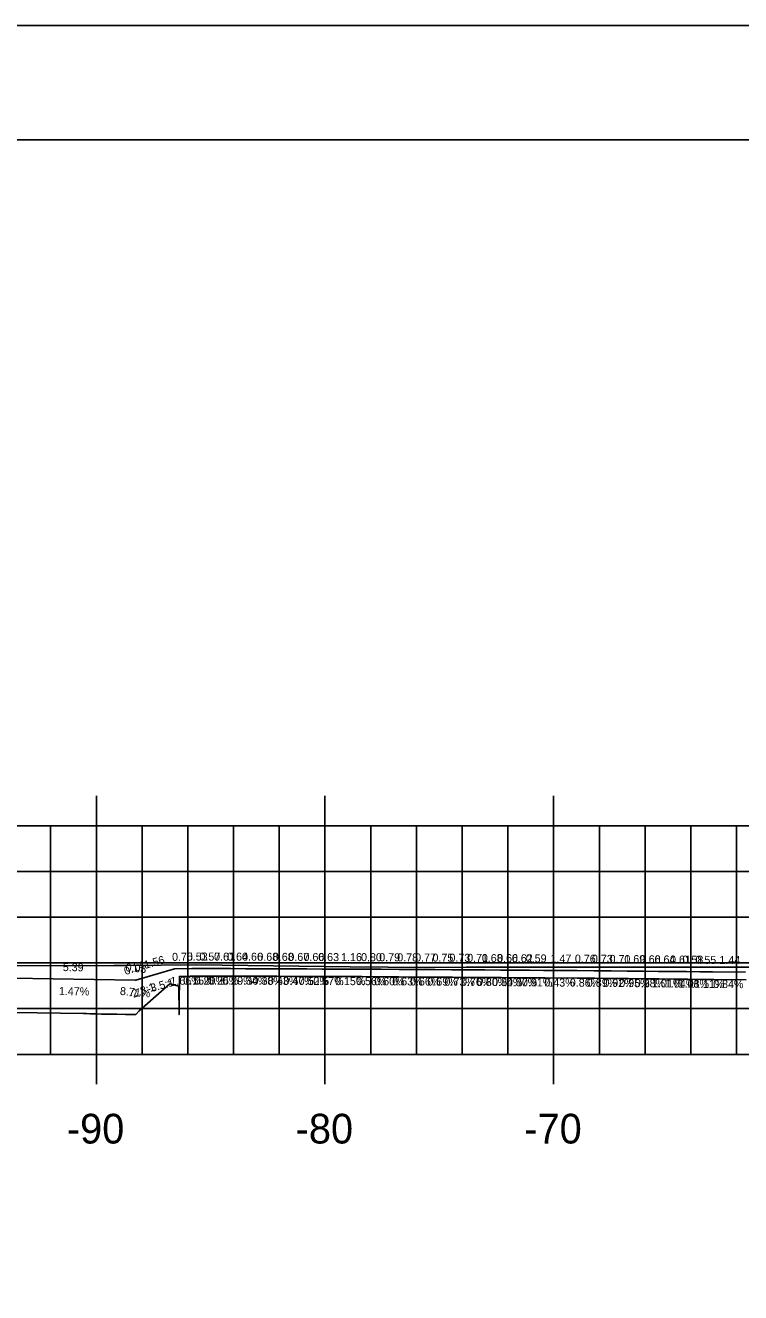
# Model space of a CAD drawing. Extents: x 40011 to 50684, y 49949 to 72236.
# Drawn here: x 41698.9 to 41730.2, y 69139.2 to 69194.6 of the extents above; entities that cross this region are included whole.
import ezdxf

# ---------------------------------------------------------------- set-up
doc = ezdxf.new("R2010")
doc.units = 0
for name, color, linetype in [('1', 7, 'Continuous'), ('10', 7, 'Continuous'), ('41', 7, 'Continuous'), ('51', 7, 'Continuous'), ('53', 7, 'Continuous'), ('55', 7, 'Continuous'), ('57', 7, 'Continuous'), ('58', 7, 'Continuous'), ('59', 7, 'Continuous'), ('60', 7, 'Continuous')]:
    doc.layers.add(name, color=color, linetype=linetype)

msp = doc.modelspace()

# ---------------------------------------------------------------- linework, layer by layer
at = {"layer": '1'}
for p, q in [((41962.978, 69194.597), (41613.588, 69194.597)), ((41961.977, 69189.597), (41631.977, 69189.597))]:
    msp.add_line(p, q, dxfattribs=at)
at = {"layer": '41'}
for points in [[(41613.588, 69194.597), (41962.978, 69194.597), (41962.978, 68974.597), (41613.588, 68974.597)], [(41631.977, 69189.597), (41961.977, 69189.597), (41961.977, 68979.597), (41631.977, 68979.597)]]:
    msp.add_lwpolyline(points, close=True, dxfattribs=at)
at = {"layer": '51'}
for p, q in [((41699.977, 69149.597), (41699.977, 69159.597)), ((41703.977, 69149.597), (41703.977, 69159.597)), ((41705.977, 69149.597), (41705.977, 69159.597)), ((41707.977, 69149.597), (41707.977, 69159.597)), ((41709.977, 69149.597), (41709.977, 69159.597)), ((41713.977, 69149.597), (41713.977, 69159.597)), ((41715.977, 69149.597), (41715.977, 69159.597)), ((41717.977, 69149.597), (41717.977, 69159.597)), ((41719.977, 69149.597), (41719.977, 69159.597)), ((41723.977, 69149.597), (41723.977, 69159.597)), ((41725.977, 69149.597), (41725.977, 69159.597)), ((41727.977, 69149.597), (41727.977, 69159.597)), ((41729.977, 69149.597), (41729.977, 69159.597)), ((41651.977, 69149.597), (41931.977, 69149.597)), ((41701.977, 69148.297), (41701.977, 69149.597)), ((41711.977, 69148.297), (41711.977, 69149.597)), ((41721.977, 69148.297), (41721.977, 69149.597))]:
    msp.add_line(p, q, dxfattribs=at)
at = {"layer": '53'}
for p, q in [((41651.977, 69157.597), (41931.977, 69157.597)), ((41651.977, 69155.597), (41931.977, 69155.597)), ((41651.977, 69153.597), (41931.977, 69153.597)), ((41651.977, 69151.597), (41931.977, 69151.597))]:
    msp.add_line(p, q, dxfattribs=at)
at = {"layer": '55'}
for p, q in [((41651.977, 69159.597), (41931.977, 69159.597)), ((41701.977, 69149.597), (41701.977, 69159.597)), ((41711.977, 69149.597), (41711.977, 69159.597)), ((41721.977, 69149.597), (41721.977, 69159.597)), ((41651.977, 69149.597), (41931.977, 69149.597))]:
    msp.add_line(p, q, dxfattribs=at)
at = {"layer": '57'}
msp.add_lwpolyline([(41698.334, 69153.465), (41702.739, 69153.489), (41703.272, 69153.487), (41706.359, 69153.506), (41713.08, 69153.417), (41716.369, 69153.398), (41718.162, 69153.413), (41733.561, 69153.402), (41740.451, 69153.466), (41742.56, 69153.498), (41743.633, 69153.542), (41747.068, 69153.548), (41758.48, 69153.677)], dxfattribs=at)
at = {"layer": '58'}
msp.add_lwpolyline([(41690.257, 69151.538), (41701.408, 69151.38), (41701.54, 69151.376), (41701.712, 69151.371), (41701.933, 69151.366), (41702.205, 69151.36), (41702.523, 69151.354), (41702.879, 69151.348), (41703.255, 69151.344), (41703.634, 69151.339), (41703.7, 69151.339), (41703.853, 69151.499), (41705.19, 69152.679), (41705.584, 69152.574), (41705.592, 69151.335), (41705.597, 69151.785), (41705.611, 69153.005), (41706.074, 69153.019), (41706.612, 69153.018), (41707.197, 69153.017), (41707.823, 69153.015), (41708.484, 69153.014), (41709.171, 69153.011), (41709.873, 69153.009), (41710.58, 69153.006), (41711.278, 69153.002), (41711.958, 69152.999), (41712.605, 69152.995), (41713.587, 69152.994), (41714.398, 69152.99), (41715.204, 69152.984), (41716, 69152.979), (41716.783, 69152.974), (41717.547, 69152.969), (41718.292, 69152.964), (41719.011, 69152.958), (41719.703, 69152.952), (41720.367, 69152.947), (41720.998, 69152.942), (41721.596, 69152.936), (41723.01, 69152.93), (41723.774, 69152.923), (41724.515, 69152.916), (41725.232, 69152.91), (41725.924, 69152.903), (41726.591, 69152.897), (41727.231, 69152.89), (41727.844, 69152.884), (41728.43, 69152.877), (41728.988, 69152.871), (41730.401, 69152.859)], dxfattribs=at)
at = {"layer": '59'}
msp.add_lwpolyline([(41698.287, 69152.922), (41703.675, 69152.842), (41703.701, 69152.84), (41703.845, 69152.891), (41705.4, 69153.335), (41706.146, 69153.347), (41706.675, 69153.347), (41707.246, 69153.346), (41707.855, 69153.344), (41708.495, 69153.342), (41709.157, 69153.34), (41709.834, 69153.337), (41710.514, 69153.334), (41711.187, 69153.331), (41711.842, 69153.328), (41712.47, 69153.324), (41713.63, 69153.323), (41714.427, 69153.318), (41715.22, 69153.313), (41716.004, 69153.308), (41716.774, 69153.303), (41717.528, 69153.298), (41718.261, 69153.293), (41718.971, 69153.287), (41719.654, 69153.282), (41720.31, 69153.276), (41720.935, 69153.271), (41721.528, 69153.265), (41723, 69153.259), (41723.756, 69153.253), (41724.49, 69153.246), (41725.201, 69153.24), (41725.888, 69153.233), (41726.55, 69153.227), (41727.185, 69153.22), (41727.794, 69153.214), (41728.376, 69153.208), (41728.93, 69153.201), (41730.366, 69153.189)], dxfattribs=at)
at = {"layer": '60'}
for p, q in [((41701.977, 69160.897), (41701.977, 69159.597)), ((41711.977, 69160.897), (41711.977, 69159.597)), ((41721.977, 69160.897), (41721.977, 69159.597))]:
    msp.add_line(p, q, dxfattribs=at)

# ---------------------------------------------------------------- texts
at = {"layer": '10'}
for s, rotation, p in [('5.39', 359.1579, (41700.507, 69153.239)), ('0.14', 19.3463, (41703.257, 69153.055)), ('0.03', 355.0199, (41703.242, 69153.232)), ('1.56', 15.9356, (41704.119, 69153.333)), ('0.75', 0.9517, (41705.291, 69153.683)), ('0.53', 359.9154, (41705.933, 69153.698)), ('0.57', 359.8864, (41706.485, 69153.697)), ('0.61', 359.8589, (41707.125, 69153.696)), ('0.64', 359.8325, (41707.696, 69153.695)), ('0.66', 359.8067, (41708.348, 69153.693)), ('0.68', 359.7813, (41709.018, 69153.691)), ('0.68', 359.7557, (41709.696, 69153.688)), ('0.67', 359.7296, (41710.375, 69153.685)), ('0.66', 359.7026, (41711.037, 69153.682)), ('0.63', 359.6741, (41711.679, 69153.679)), ('1.16', 359.9127, (41712.681, 69153.674)), ('0.80', 359.6773, (41713.553, 69153.673)), ('0.79', 359.6586, (41714.349, 69153.669)), ('0.78', 359.6399, (41715.137, 69153.664)), ('0.77', 359.621, (41715.917, 69153.659)), ('0.75', 359.6019, (41716.677, 69153.654)), ('0.73', 359.5825, (41717.42, 69153.649)), ('0.71', 359.5626, (41718.195, 69153.643)), ('0.68', 359.5421, (41718.836, 69153.638)), ('0.66', 359.5209, (41719.506, 69153.633)), ('0.62', 359.4989, (41720.149, 69153.628)), ('0.59', 359.4758, (41720.756, 69153.623)), ('1.47', 359.7527, (41721.841, 69153.614)), ('0.76', 359.5071, (41722.905, 69153.61)), ('0.73', 359.4905, (41723.65, 69153.604)), ('0.71', 359.4736, (41724.425, 69153.597)), ('0.69', 359.4563, (41725.069, 69153.591)), ('0.66', 359.4385, (41725.743, 69153.585)), ('0.64', 359.4202, (41726.391, 69153.578)), ('0.61', 359.4013, (41727.067, 69153.571)), ('0.58', 359.3817, (41727.61, 69153.566)), ('0.55', 359.3614, (41728.179, 69153.56)), ('1.44', 359.5204, (41729.224, 69153.549)), ('-1.66%', 0.9517, (41705.065, 69152.629)), ('0.15%', 359.9154, (41705.776, 69152.648)), ('0.20%', 359.8864, (41706.273, 69152.648)), ('0.25%', 359.8589, (41706.862, 69152.647)), ('1.47%', 359.1579, (41700.336, 69152.191)), ('8.71%', 355.0199, (41702.998, 69152.199)), ('-2.8:1', 19.3463, (41703.451, 69152.011)), ('-3.5:1', 15.9356, (41704.248, 69152.278)), ('0.29%', 359.8325, (41707.485, 69152.645)), ('0.34%', 359.8067, (41708.132, 69152.643)), ('0.38%', 359.7813, (41708.805, 69152.641)), ('0.43%', 359.7557, (41709.48, 69152.639)), ('0.47%', 359.7296, (41710.158, 69152.636)), ('0.52%', 359.7026, (41710.824, 69152.633)), ('0.57%', 359.6741, (41711.465, 69152.63)), ('0.15%', 359.9127, (41712.415, 69152.624)), ('0.56%', 359.6773, (41713.335, 69152.624)), ('0.60%', 359.6586, (41714.13, 69152.62)), ('0.63%', 359.6399, (41714.918, 69152.615)), ('0.66%', 359.621, (41715.694, 69152.61)), ('0.69%', 359.6019, (41716.456, 69152.606)), ('0.73%', 359.5825, (41717.202, 69152.6)), ('0.76%', 359.5626, (41717.923, 69152.595)), ('0.80%', 359.5421, (41718.62, 69152.59)), ('0.84%', 359.5209, (41719.286, 69152.585)), ('0.87%', 359.4989, (41719.93, 69152.58)), ('0.91%', 359.4758, (41720.59, 69152.574)), ('0.43%', 359.7527, (41721.57, 69152.565)), ('0.86%', 359.5071, (41722.684, 69152.562)), ('0.89%', 359.4905, (41723.428, 69152.556)), ('0.92%', 359.4736, (41724.151, 69152.549)), ('0.95%', 359.4563, (41724.849, 69152.543)), ('0.98%', 359.4385, (41725.523, 69152.537)), ('1.01%', 359.4202, (41726.281, 69152.529)), ('1.04%', 359.4013, (41726.846, 69152.524)), ('1.08%', 359.3817, (41727.444, 69152.518)), ('1.11%', 359.3614, (41728.12, 69152.51)), ('0.84%', 359.5204, (41728.952, 69152.501))]:
    msp.add_text(s, height=0.35, rotation=rotation, dxfattribs=at).set_placement(p)
at = {"layer": '51'}
for s, p in [('-90', (41700.686, 69145.697)), ('-80', (41710.693, 69145.697)), ('-70', (41720.695, 69145.697))]:
    msp.add_text(s, height=1.3, dxfattribs=at).set_placement(p)

doc.saveas('drawing.dxf')
